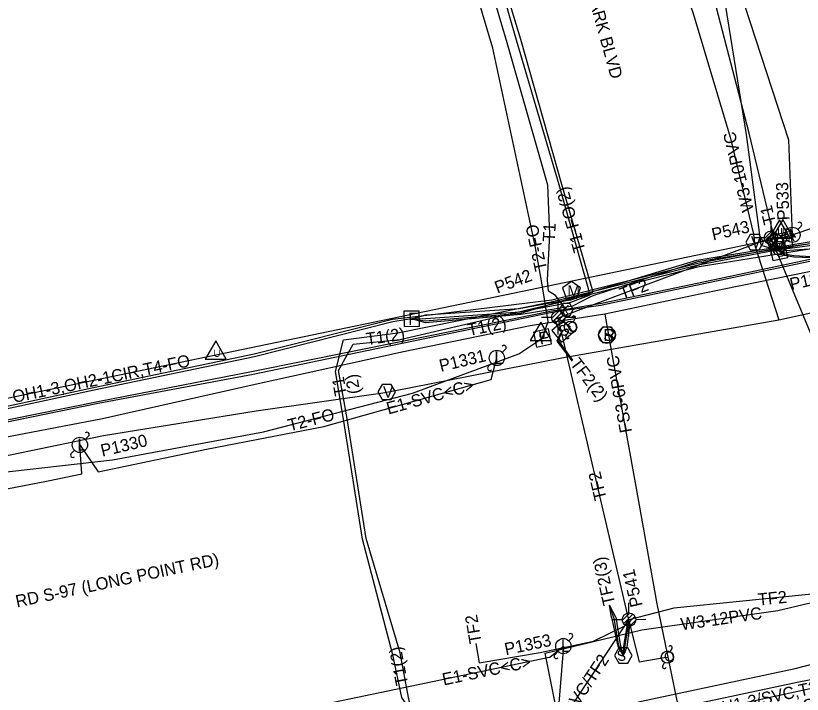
# Model space of a CAD drawing. Extents: x 2336688 to 2352634, y 362473 to 369571.
# Drawn here: x 2347760 to 2348017.1, y 367439.2 to 367661.1 of the extents above; entities that cross this region are included whole.
import ezdxf

# ---------------------------------------------------------------- set-up
doc = ezdxf.new("R2010")
doc.units = 0
for name, color, linetype in [('RD_EX_DV_Prop', 7, 'Continuous'), ('RD_EX_DV_TX_Prop', 7, 'Continuous'), ('RD_EX_RW', 7, 'Continuous'), ('RD_EX_RW_TX', 7, 'Continuous'), ('RD_HC_Data_Tic', 7, 'Continuous'), ('RD_PD_CstnLmt', 7, 'Continuous'), ('RD_PD_Final_TrvlWay', 7, 'Continuous'), ('RD_PD_FOC', 7, 'Continuous'), ('RD_PD_PatLn3', 7, 'Continuous'), ('RD_PD_PatLn4', 7, 'Continuous'), ('RD_SHT_ShtClip', 7, 'Continuous'), ('RD_Sketch1', 7, 'Continuous'), ('RD_Sketch2', 7, 'Continuous'), ('RD_Sketch5', 7, 'Continuous'), ('RD_Sketch8', 7, 'Continuous'), ('RD_TX_Misc1', 7, 'Continuous')]:
    doc.layers.add(name, color=color, linetype=linetype)

msp = doc.modelspace()

# ---------------------------------------------------------------- linework, layer by layer
at = {"layer": 'RD_EX_RW_TX'}
for points in [[(2348009.29, 367585.15), (2348008.73, 367586.49), (2348008.27, 367587.28), (2347999.79, 367622.75), (2347989.04, 367663.67), (2347975.2, 367721.77), (2347963.24, 367768.72), (2347947.28, 367808.64), (2347947, 367810.06), (2347944.42, 367816.11), (2347925.56, 367861.98), (2347909.67, 367912.79), (2347901.3, 367956.19), (2347890.84, 368007.1), (2347878.18, 368056.88)], [(2347868.44, 368054.11), (2347880, 368005.49), (2347890.68, 367955.5), (2347902.22, 367909.33), (2347920.64, 367859.94), (2347940.18, 367812), (2347959.68, 367768.1), (2347973.8, 367721.46), (2347979.06, 367711.04), (2347991.9, 367664.85), (2347998.75, 367622.27), (2348003.55, 367586.06), (2348009.9, 367584.2), (2348035.07, 367585.97), (2348081.85, 367595.07), (2348134.22, 367608.61), (2348182.28, 367613.21), (2348234.44, 367617.29), (2348281.25, 367627.74), (2348329.4, 367645.16), (2348376.54, 367659.65), (2348424.27, 367674.35), (2348472.98, 367689.81), (2348494.58, 367697.07)], [(2347889.37, 367561.99), (2347894.01, 367563.28), (2347924.61, 367565.41), (2347935.34, 367567.38), (2347941.45, 367568.25), (2347948.79, 367570.76), (2347938.54, 367605.96), (2347925.1, 367653.38), (2347910.3, 367702.18), (2347896.52, 367750.26), (2347890.46, 367772.62), (2347883.06, 367798.99), (2347870.85, 367847.44), (2347858.32, 367895.46), (2347845.4, 367943.92), (2347830.6, 367991.62), (2347817.79, 368039.88)], [(2347939.95, 367565.03), (2347936.47, 367569.65), (2347934.13, 367571), (2347933.8, 367574.63), (2347934.6, 367589.64), (2347933.91, 367605.7), (2347920.61, 367652.29), (2347906.01, 367701.68), (2347891.44, 367747.98), (2347885.27, 367770.38), (2347878.23, 367798.4), (2347866.27, 367846.38), (2347851.57, 367894.63), (2347838.48, 367943.48), (2347825.98, 367990.01), (2347822.11, 368006.53), (2347812.66, 368038.44)], [(2347889.37, 367561.99), (2347894.01, 367562.08), (2347924.79, 367564.3), (2347941.5, 367567.41), (2347947.8, 367569.8), (2347937.61, 367605.85), (2347923.72, 367653.12), (2347909.59, 367702.05), (2347895.6, 367750), (2347887.81, 367771.63), (2347880.7, 367798.16), (2347867.71, 367846.16), (2347853.69, 367894.57), (2347840.87, 367943.17), (2347827.38, 367990.48), (2347814.45, 368038.97)], [(2347470.44, 367444.23), (2347499.15, 367448.23), (2347547.38, 367460.16), (2347596.2, 367470.73), (2347644.67, 367484.24), (2347693.24, 367496.74), (2347713.15, 367501.75), (2347721.65, 367505), (2347741.52, 367510.17), (2347791.62, 367515.85), (2347841.03, 367525.03), (2347889.66, 367537.7), (2347924.48, 367550.59), (2347930.04, 367554.24), (2347932.17, 367555.74), (2347934, 367561.09), (2347931.82, 367574.4), (2347929.65, 367586.41), (2347915.95, 367650.55), (2347902.14, 367697.01)], [(2348273.75, 367646.44), (2348227.32, 367635.79), (2348178.43, 367623.86), (2348133.17, 367612.62), (2348080.1, 367600.69), (2348034.75, 367588.91), (2347982.83, 367580.63), (2347949.32, 367569.72), (2347947.83, 367569.22), (2347941.99, 367566.16), (2347925.16, 367563.38), (2347893.98, 367560.65), (2347889.37, 367561.99), (2347883.21, 367561.02), (2347838.01, 367549.55), (2347785.59, 367538.72), (2347739.47, 367528.78), (2347686.93, 367519.36), (2347638.55, 367509.72), (2347595.16, 367499.67), (2347542.86, 367488.84), (2347493.21, 367479.93), (2347455.71, 367473.66)], [(2347889.37, 367561.99), (2347893.86, 367561.38), (2347925.12, 367563.83), (2347982.59, 367581.19), (2348034.77, 367589.67), (2348080.01, 367601.39), (2348132.99, 367613.3), (2348178.17, 367624.37), (2348226.99, 367636.38), (2348274.33, 367646.97), (2348277.67, 367644.22)], [(2348277.67, 367644.22), (2348273.99, 367643.66), (2348228.58, 367631.8), (2348180.44, 367618.2), (2348135.72, 367603.5), (2348082.46, 367593.52), (2348035.48, 367584.74), (2347984.84, 367574.01), (2347951.44, 367567.02), (2347939.95, 367565.03), (2347935.77, 367564.67), (2347885.73, 367554.51), (2347837.63, 367544.73), (2347786.79, 367534.85), (2347738.82, 367525.14), (2347722.47, 367522.46), (2347720.16, 367522.7), (2347718.41, 367521.27), (2347687.23, 367515.7), (2347639.77, 367505.05), (2347596.04, 367494.09), (2347543.53, 367483.61), (2347493.77, 367474.07), (2347444.64, 367465.68)], [(2348277.67, 367644.22), (2348274.19, 367643.16), (2348263.65, 367639.56), (2348260.75, 367638.41), (2348228.6, 367631.4), (2348180.48, 367617.57), (2348135.89, 367603.05), (2348082.6, 367592.95), (2348035.55, 367584.09), (2347984.98, 367573.4), (2347951.16, 367566.33), (2347935.9, 367564.13), (2347885.75, 367553.87), (2347837.61, 367543.77), (2347786.94, 367534.28), (2347738.95, 367524.48), (2347722.65, 367521.86), (2347718.4, 367520.47), (2347687.46, 367515.07), (2347596.2, 367493.52), (2347543.48, 367483.07), (2347493.75, 367473.66), (2347444.81, 367465.06)], [(2348277.67, 367644.22), (2348273.84, 367645.8), (2348227.29, 367635.33), (2348178.6, 367623.03), (2348133.33, 367611.87), (2348080.21, 367600.2), (2348034.92, 367588.57), (2348009.29, 367585.15), (2347982.98, 367580.09), (2347935.21, 367568.08), (2347896.24, 367563.27), (2347883.18, 367561.78), (2347837.9, 367550.42), (2347785.45, 367539.42), (2347739.83, 367529.65), (2347687.13, 367520.3), (2347638.22, 367510.11), (2347594.98, 367500.2), (2347542.99, 367489.7), (2347493.07, 367480.59), (2347455.62, 367474.3)], [(2347714.77, 367382.86), (2347763.63, 367391.02), (2347811.53, 367401.75), (2347862.77, 367415.49), (2347888.44, 367419.91), (2347896.74, 367421.34), (2347897.79, 367421.54), (2347897.61, 367422.37), (2347893.27, 367425.8), (2347891.17, 367425.6), (2347888.41, 367438.13), (2347885.63, 367452.77), (2347874.57, 367490.15), (2347868.31, 367529.39), (2347865.55, 367545.13), (2347870.25, 367553.68), (2347885.67, 367555.24), (2347935.15, 367566.81), (2347983.37, 367579.12), (2348035.16, 367587.36)], [(2347720.23, 367370.45), (2347766.06, 367380.72), (2347813.13, 367394.11), (2347864.91, 367406.78), (2347888.47, 367412.88), (2347899.03, 367420.8), (2347899.5, 367421.76), (2347899.71, 367423.2), (2347898.32, 367425.13), (2347890.1, 367432.34), (2347886.2, 367438.15), (2347883.23, 367452.15), (2347873.38, 367489.92), (2347867.11, 367529.21), (2347864.56, 367544.75), (2347867.1, 367555.1), (2347884.85, 367557.4), (2347935.07, 367567.56), (2347983.07, 367579.65), (2348008.15, 367584.51), (2348034.95, 367588.04)], [(2347470.17, 367338.02), (2347527.74, 367350.46), (2347547.36, 367354.41), (2347551.42, 367355.46), (2347554.94, 367356.11), (2347601.32, 367363.67), (2347672.79, 367378.26), (2347716.22, 367388.49), (2347732.21, 367393.25), (2347737, 367394.55), (2347740.32, 367395.23), (2347763.96, 367400.82), (2347812.85, 367411.94), (2347861.88, 367418.78), (2347886.02, 367419.64), (2347912.08, 367422.89), (2347964.53, 367437), (2348014.8, 367447.66), (2348042.92, 367455.01), (2348073.57, 367461.89), (2348119.92, 367473.29), (2348155.43, 367480.43), (2348206.38, 367490.17), (2348251.79, 367501.21)], [(2348044, 367448.64), (2348015.43, 367443.03), (2347990.39, 367437.77), (2347964.96, 367432.37), (2347912.55, 367421.46), (2347898.51, 367425.33), (2347882.92, 367430.65), (2347859.25, 367426.6), (2347812.67, 367417.74), (2347762.8, 367405.7), (2347714.95, 367393.51)]]:
    msp.add_lwpolyline(points, dxfattribs=at)
for points in [[(2348008.27, 367590.28), (2348005.42, 367588.21), (2348006.51, 367584.85), (2348010.04, 367584.85), (2348011.13, 367588.21)], [(2348013.11, 367590.52), (2348008.21, 367589.51), (2348009.22, 367584.62), (2348014.12, 367585.62)], [(2348006.98, 367585.15), (2348008.14, 367583.15), (2348010.45, 367583.15), (2348011.6, 367585.15), (2348010.45, 367587.15), (2348008.14, 367587.15)], [(2347937.64, 367565.03), (2347938.79, 367563.03), (2347941.1, 367563.03), (2347942.26, 367565.03), (2347941.1, 367567.03), (2347938.79, 367567.03)], [(2347891.89, 367564.56), (2347886.89, 367564.49), (2347886.95, 367559.49), (2347891.95, 367559.56)], [(2347934.11, 367558.69), (2347929.21, 367557.68), (2347930.22, 367552.78), (2347935.12, 367553.79)]]:
    msp.add_lwpolyline(points, close=True, dxfattribs=at)
at = {"layer": 'RD_HC_Data_Tic'}
for p, q in [((2348006.89, 367590.73), (2348006.89, 367594.01)), ((2348016.74, 367592.3), (2348015.68, 367591.24)), ((2348007.19, 367590.71), (2348004.7, 367588.21)), ((2348008.2, 367590.3), (2348005.1, 367587.2)), ((2348008.86, 367589.54), (2348005.86, 367586.55)), ((2348004.68, 367588.51), (2348001.37, 367588.5)), ((2348009.11, 367588.38), (2348007.03, 367586.3)), ((2348012.42, 367588.52), (2348009.11, 367588.51)), ((2348012.14, 367587.7), (2348011.08, 367586.64)), ((2348006.89, 367583.01), (2348006.89, 367586.29)), ((2347937.35, 367564.63), (2347937.35, 367567.91)), ((2347937.65, 367564.61), (2347935.16, 367562.11)), ((2347938.66, 367564.2), (2347935.56, 367561.1)), ((2347935.14, 367562.41), (2347931.83, 367562.4)), ((2347939.31, 367563.44), (2347936.32, 367560.45)), ((2347939.57, 367562.28), (2347937.48, 367560.2)), ((2347942.88, 367562.42), (2347939.57, 367562.41)), ((2347942.32, 367561), (2347942.88, 367562.06)), ((2347937.35, 367556.91), (2347937.35, 367560.19)), ((2347939.87, 367556.41), (2347940.44, 367557.47)), ((2347919.03, 367550.97), (2347920.09, 367552.03)), ((2347914.43, 367546.37), (2347915.49, 367547.43)), ((2347782.72, 367522.55), (2347783.78, 367523.61)), ((2347778.12, 367517.95), (2347779.18, 367519.01)), ((2347960.46, 367465.83), (2347960.46, 367469.12)), ((2347958.25, 367463.61), (2347954.93, 367463.61)), ((2347960.76, 367465.81), (2347958.27, 367463.32)), ((2347961.77, 367465.41), (2347958.67, 367462.31)), ((2347962.42, 367464.65), (2347959.43, 367461.66)), ((2347962.68, 367463.49), (2347960.59, 367461.4)), ((2347965.99, 367463.63), (2347962.68, 367463.62)), ((2347960.46, 367458.12), (2347960.46, 367461.4)), ((2347940.77, 367456.74), (2347941.83, 367457.8)), ((2347936.18, 367452.15), (2347937.24, 367453.21)), ((2347973.96, 367453.15), (2347974.53, 367454.21)), ((2347971.51, 367448.56), (2347972.08, 367449.62))]:
    msp.add_line(p, q, dxfattribs=at)
msp.add_lwpolyline([(2348014.3, 367587.46), (2348013.48, 367589.47), (2348014.93, 367588.67), (2348013.06, 367591.35), (2348013.06, 367591.35), (2348014.26, 367589.26), (2348012.88, 367590.06)], close=True, dxfattribs=at)
for centre, radius in [((2348013.91, 367589.47), 2.5), ((2348006.89, 367588.51), 2.22), ((2347937.35, 367562.41), 2.22), ((2347941.38, 367559.24), 2), ((2347917.26, 367549.2), 2.5), ((2347780.95, 367520.78), 2.5), ((2347960.46, 367463.62), 2.22), ((2347939.01, 367454.97), 2.5), ((2347973.02, 367451.38), 2)]:
    msp.add_circle(centre, radius, dxfattribs=at)
for centre, radius, start, end in [((2348016.21, 367592.83), 0.75, 315, 135), ((2348011.61, 367586.11), 0.75, 135, 315), ((2347942.36, 367562.34), 0.6, 331.9175, 151.9175), ((2347940.4, 367556.13), 0.6, 151.9175, 331.9175), ((2347919.56, 367552.56), 0.75, 315, 135), ((2347914.96, 367545.84), 0.75, 135, 315), ((2347783.25, 367524.14), 0.75, 315, 135), ((2347778.65, 367517.42), 0.75, 135, 315), ((2347941.3, 367458.33), 0.75, 315, 135), ((2347974, 367454.49), 0.6, 331.9175, 151.9175), ((2347936.71, 367451.62), 0.75, 135, 315), ((2347972.04, 367448.28), 0.6, 151.9175, 331.9175)]:
    msp.add_arc(centre, radius, start, end, dxfattribs=at)
at = {"layer": 'RD_PD_Final_TrvlWay'}
for points in [[(2347411.66, 367432.11), (2347416.41, 367427.52), (2347456.82, 367435.65), (2347514.93, 367449.13), (2347514.86, 367455.85), (2347518.86, 367450.04), (2347527.31, 367452), (2347598.1, 367470.08), (2347638.25, 367479.98), (2347637.21, 367489.58), (2347641.7, 367480.84), (2347702.59, 367495.22), (2347742.38, 367503.56), (2347770.63, 367508.97), (2347781.57, 367511.28), (2347780.95, 367520.78), (2347786.97, 367511.95), (2347822.4, 367519.43), (2347860.67, 367526.84), (2347915.43, 367542.21), (2347917.26, 367549.2)], [(2347673.31, 367399.66), (2347678.14, 367397.96), (2347796.1, 367422.52), (2347799.13, 367419.97), (2347801.17, 367423.58), (2347934.37, 367451.31), (2347934.6, 367451.36), (2347939.01, 367454.97), (2347937.23, 367432.36), (2347932.97, 367422.33)]]:
    msp.add_lwpolyline(points, dxfattribs=at)
at = {"layer": 'RD_PD_FOC'}
for p, q in [((2347954.06, 367468.38), (2347955.75, 367463.32)), ((2347954.77, 367464.28), (2347954.06, 367468.38)), ((2347956.17, 367464.45), (2347954.06, 367468.38))]:
    msp.add_line(p, q, dxfattribs=at)
at = {"layer": 'RD_PD_PatLn3'}
for points in [[(2348010.7, 367594.53), (2348007.24, 367588.53), (2348014.17, 367588.53)], [(2348009.69, 367594.41), (2348006.22, 367588.41), (2348013.15, 367588.41)], [(2347931.62, 367560.9), (2347928.15, 367554.9), (2347935.08, 367554.9)], [(2347825.37, 367554.77), (2347821.9, 367548.77), (2347828.83, 367548.77)]]:
    msp.add_lwpolyline(points, close=True, dxfattribs=at)
at = {"layer": 'RD_SHT_ShtClip'}
for p, q in [((2347721.34, 367528.63), (2348013.81, 367589.41)), ((2347937.29, 367562.34), (2348006.83, 367588.44)), ((2348006.83, 367588.44), (2348054.67, 367473.05)), ((2347960.39, 367463.55), (2347937.29, 367562.34)), ((2347932.97, 367422.33), (2347960.39, 367463.55)), ((2347932.97, 367422.33), (2348085.42, 367455.46))]:
    msp.add_line(p, q, dxfattribs=at)
for points in [[(2347943.25, 367806.04), (2347960.57, 367780.14), (2348012.56, 367620.55), (2348013.81, 367589.41)], [(2348302.69, 367654.16), (2348290.76, 367652.88), (2348289.31, 367651.06), (2348287.96, 367652.58), (2348257.65, 367649.33), (2348056.6, 367604.27), (2348013.81, 367589.41)], [(2348054.67, 367473.05), (2348039.51, 367473.91), (2347975.08, 367467.41), (2347960.39, 367463.55)]]:
    msp.add_lwpolyline(points, dxfattribs=at)
at = {"layer": 'RD_Sketch2'}
for points in [[(2347862.4, 368053.55), (2347875.72, 368004.38), (2347889.43, 367955.72), (2347903.08, 367908.55), (2347917.33, 367858.5), (2347931.68, 367809.35), (2347946.76, 367763.68), (2347963.93, 367711.37), (2347966.93, 367703.46), (2347981.46, 367661.87), (2347993.5, 367621.37), (2348001.18, 367589.64), (2348001.58, 367585.97), (2348009.43, 367561.67)], [(2347449.95, 367449.7), (2347496.38, 367458.28), (2347547.67, 367468.78), (2347595.96, 367479.29), (2347606, 367481.2), (2347641.64, 367490.61), (2347690.17, 367503.64), (2347702.37, 367506.83), (2347705.77, 367507.63), (2347740.68, 367513.89), (2347788.69, 367523.87), (2347838.62, 367531.94), (2347879.94, 367537.81), (2347883.63, 367538.5), (2347938.54, 367549.3), (2348009.43, 367561.67), (2348086.12, 367578.47), (2348135.82, 367588.03), (2348185.16, 367600.49), (2348233.5, 367612.99), (2348282.05, 367625.96)], [(2347470.35, 367337.23), (2347531.2, 367351.47), (2347577.01, 367360.75), (2347616.5, 367369.7), (2347668.2, 367379.09), (2347714.88, 367387.21), (2347764.3, 367397.77), (2347812.02, 367409.64), (2347861.32, 367422.45), (2347913.79, 367430.89), (2347937.03, 367433), (2347933.07, 367452.68), (2347964.62, 367460.29), (2348009.08, 367466.62), (2348042.26, 367474.52), (2348049.97, 367475.89), (2348057.53, 367476.89), (2348069.08, 367477.92), (2348103, 367487.1), (2348151.7, 367499.89), (2348204.32, 367511.65), (2348252.13, 367524.59)]]:
    msp.add_lwpolyline(points, dxfattribs=at)
for points in [[(2348004.43, 367587.1), (2348002.99, 367589.6), (2348000.1, 367589.6), (2347998.66, 367587.1), (2348000.1, 367584.6), (2348002.99, 367584.6)], [(2347941.66, 367574.26), (2347938.76, 367572.15), (2347939.87, 367568.74), (2347943.45, 367568.74), (2347944.56, 367572.15)], [(2347884.14, 367538.08), (2347882.69, 367540.57), (2347879.81, 367540.57), (2347878.36, 367538.08), (2347879.81, 367535.58), (2347882.69, 367535.58)]]:
    msp.add_lwpolyline(points, close=True, dxfattribs=at)
at = {"layer": 'RD_Sketch5'}
for points in [[(2347445.27, 367463.42), (2347494.44, 367469.25), (2347544.4, 367476.73), (2347594.33, 367486.36), (2347688.22, 367508.14), (2347739.9, 367520.09), (2347788.33, 367529.45), (2347838.31, 367540.64), (2347886.7, 367551.33), (2347928.19, 367559.84), (2347952.54, 367563.69), (2347985.72, 367570.62), (2348036.5, 367580.92), (2348083.37, 367589.22), (2348136.57, 367600.6), (2348182.34, 367611.84), (2348232.74, 367624.03), (2348279.47, 367637.63), (2348326.25, 367651.54), (2348374.55, 367665.64), (2348421.71, 367681.15), (2348468.93, 367697.05), (2348491.54, 367705.13)], [(2347952.57, 367563.69), (2347952.6, 367563.53), (2347954.79, 367551.06), (2347962.49, 367508.35), (2347969.55, 367468.84), (2347978.45, 367425.53), (2347993.78, 367361.64), (2348002.84, 367311.48), (2348007.49, 367271.6), (2348009.48, 367222.84), (2348015.7, 367168.77), (2348038.63, 367106.93)]]:
    msp.add_lwpolyline(points, dxfattribs=at)
msp.add_lwpolyline([(2347956.14, 367556.73), (2347954.7, 367559.23), (2347951.81, 367559.23), (2347950.37, 367556.73), (2347951.81, 367554.23), (2347954.7, 367554.23)], close=True, dxfattribs=at)
msp.add_circle((2347953.25, 367556.73), 2.75, dxfattribs=at)
at = {"layer": 'RD_Sketch8'}
for points in [[(2348006.44, 367588.48), (2348005.7, 367588.35), (2348006.64, 367586.78), (2348008.66, 367584.85), (2348011.35, 367582.82), (2348014.33, 367582.26), (2348020.03, 367582.02), (2348039.02, 367584.95), (2348043.19, 367583.03), (2348055.21, 367577.57), (2348058.18, 367576.27), (2348059.81, 367576.13)], [(2348006.44, 367588.48), (2348006.73, 367587.58), (2348011.23, 367583.23), (2348014.34, 367582.74), (2348019.96, 367582.43), (2348038.9, 367585.3), (2348043.5, 367583.53), (2348055.57, 367577.93), (2348058.42, 367576.65), (2348059.81, 367576.13)], [(2347938.72, 367557.92), (2347937.26, 367559.09), (2347936.13, 367561.79), (2347937.29, 367562.34)], [(2347941.38, 367559.24), (2347940.31, 367559.99), (2347937.55, 367561.89), (2347937.29, 367562.34)], [(2347938.72, 367557.92), (2347937.91, 367557.09), (2347936.9, 367554.65), (2347941.88, 367548.12)], [(2347938.72, 367557.92), (2347938.13, 367556.97), (2347937.36, 367554.93), (2347941.95, 367548.47)], [(2347910.37, 367455.82), (2347911.51, 367449.55), (2347931.4, 367452.93), (2347948.85, 367456.64), (2347959.08, 367461.59), (2347960.39, 367463.55)], [(2347954.77, 367464.28), (2347956.86, 367454.99), (2347958.59, 367451.94)], [(2347956.17, 367464.45), (2347957.53, 367455.5), (2347958.59, 367451.94)], [(2347960.39, 367463.55), (2347959.62, 367460.69), (2347958.7, 367454.93), (2347958.59, 367451.94)], [(2347958.59, 367451.94), (2347959.12, 367454.55), (2347960.07, 367460.7), (2347960.39, 367463.55)], [(2347960.39, 367463.55), (2347960.51, 367460.94), (2347959.72, 367454.66), (2347958.59, 367451.94)], [(2347960.39, 367463.55), (2347960.94, 367461.1), (2347963.79, 367449.8), (2347971.95, 367451.22), (2347973.02, 367451.38)], [(2347958.59, 367451.94), (2347957.09, 367455.08), (2347955.75, 367463.32)]]:
    msp.add_lwpolyline(points, dxfattribs=at)
for points in [[(2348011.39, 367586.95), (2348006.49, 367585.95), (2348007.48, 367581.05), (2348012.38, 367582.05)], [(2347939, 367561.44), (2347935.19, 367558.2), (2347938.44, 367554.39), (2347942.24, 367557.64)], [(2347955.71, 367451.94), (2347957.15, 367449.44), (2347960.04, 367449.44), (2347961.48, 367451.94), (2347960.04, 367454.44), (2347957.15, 367454.44)]]:
    msp.add_lwpolyline(points, close=True, dxfattribs=at)

# ---------------------------------------------------------------- texts
at = {"layer": 'RD_EX_DV_Prop'}
for rotation, p in [(15.676, (2347881.81, 367530.69)), (11.7605, (2347899.87, 367442.08))]:
    msp.add_text('E1-SVC<C>', height=4, rotation=rotation, dxfattribs=at).set_placement(p)
at = {"layer": 'RD_EX_DV_TX_Prop'}
for s, rotation, p in [('P533', 92.3071, (2348012.96, 367594.3)), ('P543', 12.6337, (2347987.97, 367587.61)), ('P542', 20.5706, (2347917.42, 367570.22)), ('P1333', 12.8877, (2348013.52, 367571.34)), ('P1331', 13.2952, (2347898.95, 367544.65)), ('P1330', 13.2952, (2347788.28, 367516.91)), ('P541', 103.1654, (2347964.97, 367468.25)), ('P1353', 11.7539, (2347920.21, 367451.97))]:
    msp.add_text(s, height=4, rotation=rotation, dxfattribs=at).set_placement(p)
at = {"layer": 'RD_EX_RW'}
for s, rotation, p in [('T1-FO(2)', 105.7759, (2347946.33, 367584.38)), ('T1', 103.4517, (2348008.53, 367593.35)), ('T2-FO', 102.0589, (2347933.74, 367578.09)), ('T1', 86.9335, (2347936.21, 367587.08)), ('T1(2)', 11.5611, (2347908.17, 367556.36)), ('T1(2)', 8.0656, (2347874.78, 367553.4)), ('T1', 99.944, (2347868.29, 367537.15)), ('(2)', 99.944, (2347872.65, 367537.75)), ('T2-FO', 14.1493, (2347849.52, 367525.17)), ('T1(2)', 100.7354, (2347888.28, 367442.52))]:
    msp.add_text(s, height=4, rotation=rotation, dxfattribs=at).set_placement(p)
at = {"layer": 'RD_EX_RW_TX'}
for s, height, rotation, p in [('F', 4, 11.6256, (2348010.46, 367585.38)), ('X', 3, 180, (2348010.24, 367586.65)), ('X', 3, 180, (2347940.89, 367566.53)), ('F', 4, 0.7793, (2347888.31, 367560.01)), ('F', 4, 11.6256, (2347931.46, 367553.55))]:
    msp.add_text(s, height=height, rotation=rotation, dxfattribs=at).set_placement(p)
msp.add_text('T', height=3.75, dxfattribs=at).set_placement((2348007.04, 367585.05))
at = {"layer": 'RD_HC_Data_Tic'}
for s, height, rotation, p in [('O', 3.2, 16.9175, (2347940.86, 367557.4)), ('L', 4, 360, (2347916.45, 367547.27)), ('L', 4, 360, (2347780.14, 367518.85)), ('L', 4, 360, (2347938.19, 367453.04)), ('O', 3.2, 16.9175, (2347972.5, 367449.55))]:
    msp.add_text(s, height=height, rotation=rotation, dxfattribs=at).set_placement(p)
at = {"layer": 'RD_PD_CstnLmt'}
for s, rotation, p in [('W3-10PVC', 103.5936, (2348001.34, 367597.49)), ('W3-12PVC', 8.1, (2347977.67, 367460.13))]:
    msp.add_text(s, height=4, rotation=rotation, dxfattribs=at).set_placement(p)
at = {"layer": 'RD_PD_FOC'}
for s, rotation, p in [('TF2(2)', 307.4001, (2347940.99, 367547.3)), ('TF2(3)', 102.7018, (2347956.01, 367468.82)), ('TF2', 99.6262, (2347912.34, 367456.15))]:
    msp.add_text(s, height=4, rotation=rotation, dxfattribs=at).set_placement(p)
at = {"layer": 'RD_PD_PatLn3'}
for p in [(2348008.93, 367589.21), (2348009.95, 367589.33), (2347930.86, 367555.7), (2347824.61, 367549.57)]:
    msp.add_text('U', height=2.4, dxfattribs=at).set_placement(p)
at = {"layer": 'RD_PD_PatLn4'}
for s, rotation, p in [('TF2', 20.5706, (2347958.29, 367568.09)), ('OH1-3,OH2-1CIR,T4-FO', 11.7386, (2347759.36, 367534.49)), ('TF2', 103.1654, (2347953.19, 367503.14)), ('TF2', 5.7537, (2348002.8, 367468.2)), ('SVC/TF2', 56.3634, (2347941.97, 367432.27)), ('OH1-3/SVC,T2-FO,', 12.2611, (2347987.3, 367432.09)), ('TV1-C/FO,TV2-C/FO,TF2', 12.2611, (2347981.09, 367425.41))]:
    msp.add_text(s, height=4, rotation=rotation, dxfattribs=at).set_placement(p)
at = {"layer": 'RD_Sketch1'}
msp.add_text('FS3-6PVC', height=4, rotation=100.1903, dxfattribs=at).set_placement((2347961.49, 367525.11))
at = {"layer": 'RD_Sketch2'}
for s, p in [('V', (2348000.33, 367585.22)), ('M', (2347940.29, 367569.22)), ('V', (2347880.04, 367536.2))]:
    msp.add_text(s, height=3.75, dxfattribs=at).set_placement(p)
at = {"layer": 'RD_Sketch5'}
for s, height, p in [('S', 3.93, (2347952.05, 367554.77)), ('R', 4, (2347952.03, 367554.73))]:
    msp.add_text(s, height=height, rotation=360, dxfattribs=at).set_placement(p)
at = {"layer": 'RD_Sketch8'}
for rotation, p in [(11.458, (2348008.72, 367582.05)), (40.486, (2347939.04, 367555.87)), (180, (2347959.68, 367453.71))]:
    msp.add_text('S', height=3.53, rotation=rotation, dxfattribs=at).set_placement(p)
at = {"layer": 'RD_TX_Misc1'}
for s, rotation, p in [('WANDO PARK BLVD', 285.5754, (2347940.68, 367690.26)), ('RD S-97 (LONG POINT RD)', 11.8928, (2347760.39, 367467.59))]:
    msp.add_text(s, height=4, rotation=rotation, dxfattribs=at).set_placement(p)

doc.saveas('drawing.dxf')
